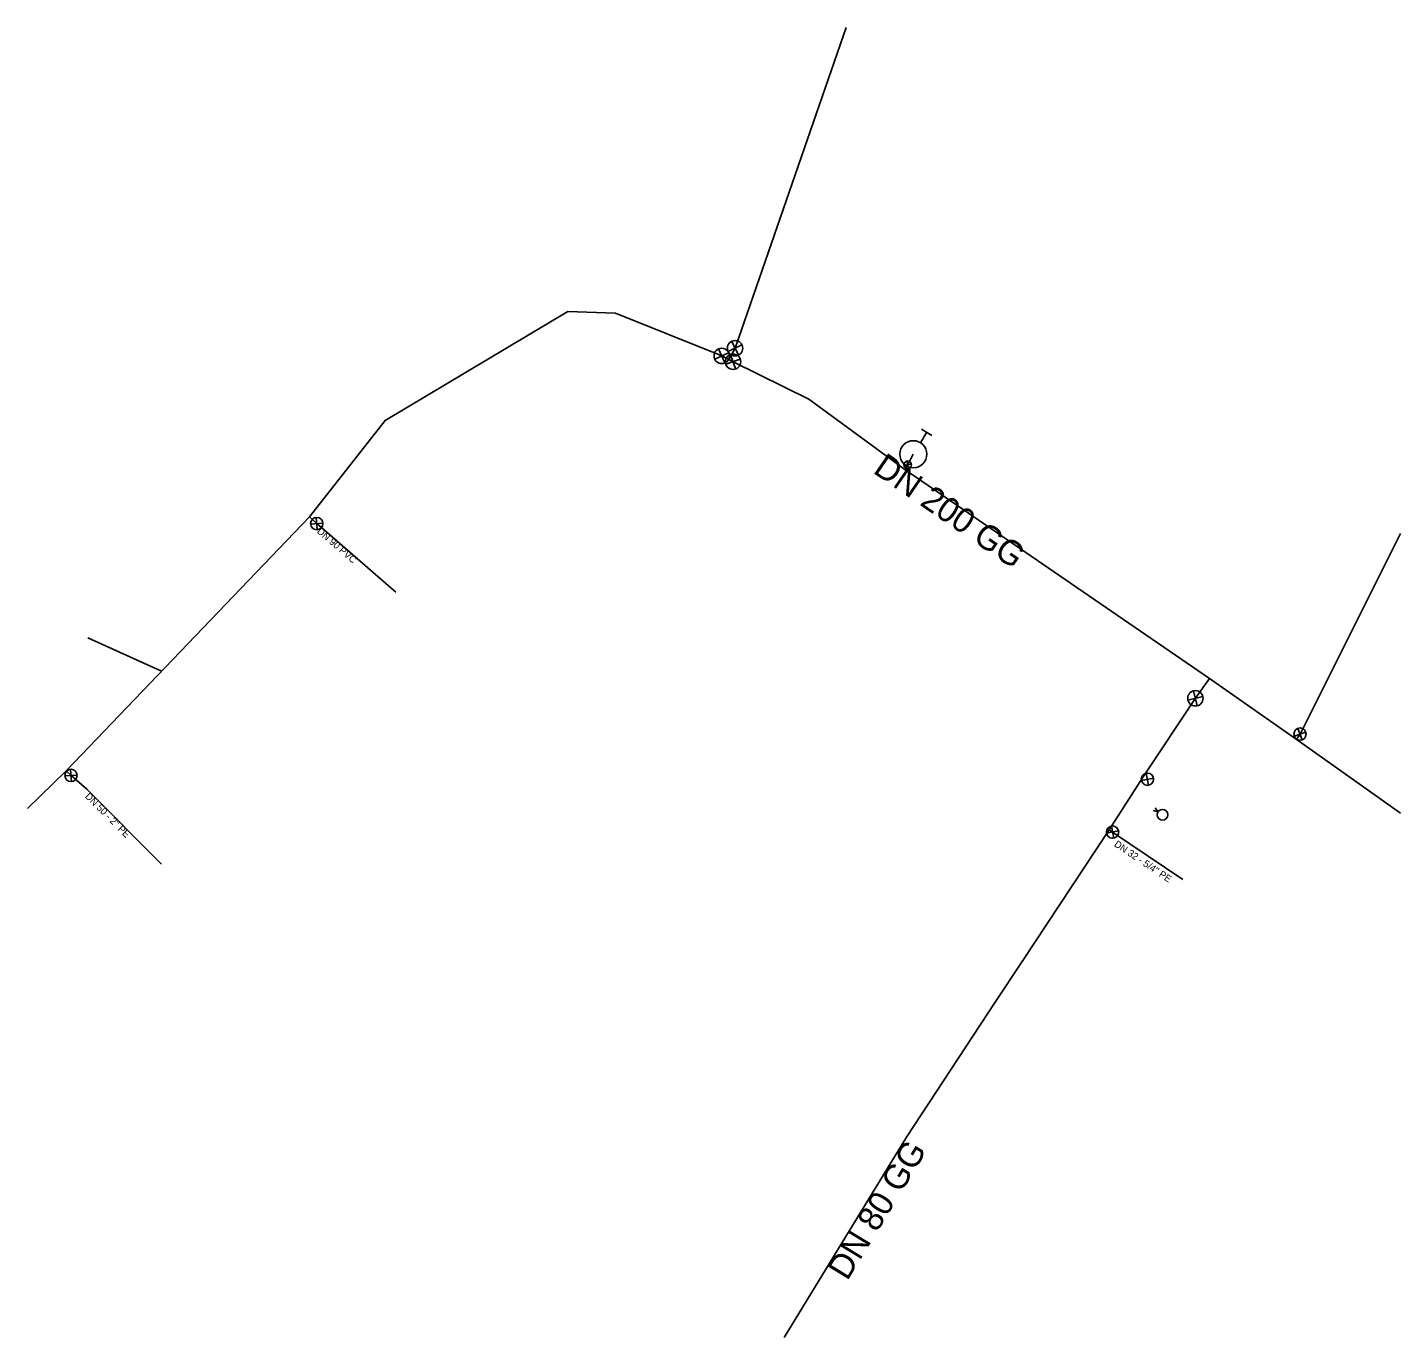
# Model space of a CAD drawing. Extents: x -496908.3 to -496818.9, y -1087776.3 to -1087691.
import ezdxf

# ---------------------------------------------------------------- set-up
doc = ezdxf.new("R2010")
doc.units = 0
for name, color, linetype in [('_hydrantova_odbocka_', 7, 'Continuous'), ('_pripojka_prevzato_z_dokumentace_', 7, 'Continuous'), ('_pripojka_priblizne_', 7, 'Continuous'), ('_voda_smvak_prevzato_z_dokumentace_', 7, 'Continuous'), ('Default', 7, 'Continuous'), ('MoLevel 27', 7, 'Continuous'), ('MoLevel 28', 7, 'Continuous'), ('MoLevel 30', 7, 'Continuous'), ('MoLevel 46', 7, 'Continuous'), ('MoLevel 53', 7, 'Continuous'), ('MoLevel 55', 7, 'Continuous')]:
    doc.layers.add(name, color=color, linetype=linetype)

# ---------------------------------------------------------------- blocks, each defined once
blk = doc.blocks.new('_uzaver_')
at = {"layer": 'Default'}
for p, q in [((-0.000035, -0.000035), (0.000035, 0.000035)), ((0.000035, -0.000035), (-0.000035, 0.000035))]:
    blk.add_line(p, q, dxfattribs=at)
for radius in [0.00005, 0.0000025]:
    blk.add_circle((0, 0), radius, dxfattribs=at)
blk = doc.blocks.new('_uzaver_pripojka_')
at = {"layer": 'Default'}
for p, q in [((-0.000035, -0.000035), (0.000035, 0.000035)), ((0.000035, -0.000035), (-0.000035, 0.000035))]:
    blk.add_line(p, q, dxfattribs=at)
for radius in [0.00005, 0.0000025]:
    blk.add_circle((0, 0), radius, dxfattribs=at)
blk = doc.blocks.new('_hydrant_voda_')
at = {"layer": 'Default'}
for p, q in [((-0.0000225, 0.000095), (0.0000225, 0.000095)), ((0, 0.000095), (0, 0.00005))]:
    blk.add_line(p, q, dxfattribs=at)
blk.add_circle((0, 0), 0.00005, dxfattribs=at)
blk = doc.blocks.new('_sachta_voda_')
at = {"layer": 'Default'}
blk.add_lwpolyline([(-0.00001, 0.000065), (0, 0.000035), (0.00001, 0.000065)], dxfattribs=at)
blk.add_circle((0, 0), 0.000035, dxfattribs=at)

msp = doc.modelspace()

# ---------------------------------------------------------------- linework, layer by layer
at = {"layer": '_hydrantova_odbocka_'}
msp.add_lwpolyline([(-496851.16, -1087719.81), (-496850.96, -1087719.51), (-496850.6, -1087718.82)], dxfattribs=at)
at = {"layer": '_pripojka_prevzato_z_dokumentace_'}
for points in [[(-496889.9, -1087722.89), (-496889.43, -1087723.34), (-496884.285, -1087727.802)], [(-496825.667, -1087737.375), (-496825.43, -1087737.04), (-496818.887, -1087723.977)], [(-496905.74, -1087739.43), (-496905.42, -1087739.73), (-496904.4, -1087740.63), (-496899.52, -1087745.5)], [(-496837.86, -1087743.28), (-496837.63, -1087743.42), (-496833.05, -1087746.51)]]:
    msp.add_lwpolyline(points, dxfattribs=at)
at = {"layer": '_pripojka_priblizne_'}
msp.add_line((-496899.529, -1087732.944), (-496904.315, -1087730.767), dxfattribs=at)
at = {"layer": '_voda_smvak_prevzato_z_dokumentace_'}
for p, q in [((-496862.2, -1087711.92), (-496854.973, -1087691.036)), ((-496862.6, -1087712.66), (-496862.2, -1087711.92)), ((-496862.6, -1087712.66), (-496863.07, -1087712.42)), ((-496862.6, -1087712.66), (-496862.33, -1087712.8)), ((-496851.16, -1087719.81), (-496831.32, -1087733.42)), ((-496831.32, -1087733.42), (-496832.24, -1087734.71))]:
    msp.add_line(p, q, dxfattribs=at)
for points in [[(-496863.07, -1087712.42), (-496869.979, -1087709.638), (-496873.08, -1087709.52), (-496884.98, -1087716.62), (-496889.9, -1087722.89), (-496905.74, -1087739.43), (-496908.254, -1087741.887)], [(-496862.33, -1087712.8), (-496857.4, -1087715.23), (-496851.16, -1087719.81)], [(-496818.887, -1087742.18), (-496825.678, -1087737.367), (-496831.32, -1087733.42)], [(-496832.24, -1087734.71), (-496835.63, -1087739.82), (-496837.86, -1087743.28), (-496843.504, -1087751.838)], [(-496843.504, -1087751.838), (-496845.26, -1087754.5), (-496851.05, -1087763.29), (-496859.001, -1087776.327)]]:
    msp.add_lwpolyline(points, dxfattribs=at)

# ---------------------------------------------------------------- block references
at = {"layer": 'MoLevel 27'}
for p, xscale, yscale, rotation in [((-496862.2, -1087711.92), 9999.999999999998, 10000, 71.0306354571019), ((-496863.07, -1087712.42), 10000.000000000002, 10000, 159.150592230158), ((-496862.33, -1087712.8), 10000, 10000, -25.83150398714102), ((-496850.96, -1087719.51), 5000, 4999.999999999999, 57.3005388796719), ((-496832.24, -1087734.71), 10000, 10000, 58.36866388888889)]:
    msp.add_blockref('_uzaver_', p, dxfattribs=dict(at, xscale=xscale, yscale=yscale, rotation=rotation))
at = {"layer": 'MoLevel 28', "xscale": 17636.68430335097, "yscale": 17636.684303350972, "rotation": -31.57981643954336}
msp.add_blockref('_hydrant_voda_', (-496850.6, -1087718.82), dxfattribs=at)
at = {"layer": 'MoLevel 30', "xscale": 10000, "yscale": 10000, "rotation": 56.33051666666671}
msp.add_blockref('_sachta_voda_', (-496834.38, -1087742.29), dxfattribs=at)
at = {"layer": 'MoLevel 53'}
for p, xscale, yscale, rotation in [((-496889.43, -1087723.34), 7999.999999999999, 7999.999999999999, -41.22536944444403), ((-496825.43, -1087737.04), 8000, 8000, 65.0715027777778), ((-496905.42, -1087739.73), 7999.999999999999, 8000, -41.44563626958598), ((-496835.36, -1087739.98), 7999.999999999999, 7999.999999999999, -33.664311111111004), ((-496837.63, -1087743.42), 8000, 8000, -34.006456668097)]:
    msp.add_blockref('_uzaver_pripojka_', p, dxfattribs=dict(at, xscale=xscale, yscale=yscale, rotation=rotation))

# ---------------------------------------------------------------- texts
at = {"layer": 'MoLevel 46'}
for s, rotation, p in [('DN 200 GG', 325.55035, (-496853.289, -1087719.991)), ('DN 80 GG', 58.62057, (-496854.898, -1087772.681))]:
    msp.add_text(s, height=1.6049, rotation=rotation, dxfattribs=at).set_placement(p)
at = {"layer": 'MoLevel 55'}
for s, rotation, p in [('DN 90 PVC', 319.06383, (-496889.446, -1087723.899)), ("DN 50 - 2'' PE", 315.05877, (-496904.541, -1087741.132)), ("DN 32 - 5/4'' PE", 325.99355, (-496837.568, -1087744.308))]:
    msp.add_text(s, height=0.455, rotation=rotation, dxfattribs=at).set_placement(p)

doc.saveas('drawing.dxf')
